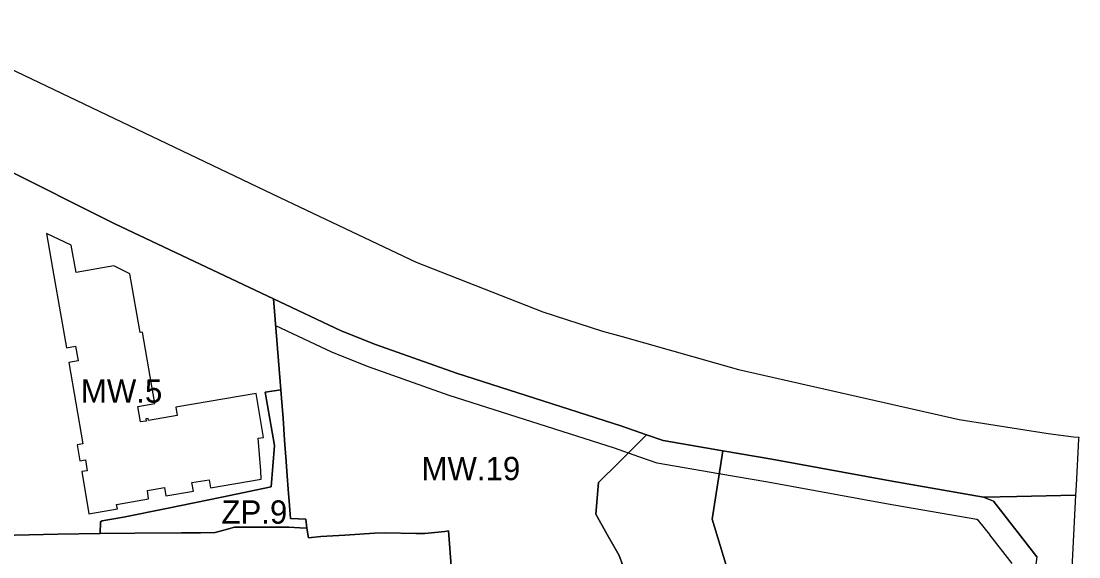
# Model space of a CAD drawing. Extents: x 7429178 to 7430831, y 5550228 to 5551611.
# Drawn here: x 7430227.9 to 7430454.6, y 5551215.2 to 5551330.1 of the extents above; entities that cross this region are included whole.
import ezdxf

# ---------------------------------------------------------------- set-up
doc = ezdxf.new("R2010")
doc.units = 0
for name, color, linetype in [('linie rozgraniczające', 7, 'Continuous'), ('nieprzekraczalne linie zabudowy', 7, 'Continuous'), ('obowiazujace linie zabudowy', 7, 'Continuous'), ('przeznaczenia terenów', 7, 'Continuous')]:
    doc.layers.add(name, color=color, linetype=linetype)

msp = doc.modelspace()

# ---------------------------------------------------------------- linework, layer by layer
at = {"layer": 'linie rozgraniczające'}
for points in [[(7430204.21, 5551330.07), (7430283.32, 5551292.27), (7430287.53, 5551290.26), (7430312.6, 5551278.38), (7430339.69, 5551267.71), (7430352.52, 5551263.63), (7430356.74, 5551262.44), (7430381.68, 5551255.38), (7430428.93, 5551244.66), (7430448.02, 5551241.65), (7430453.5, 5551240.96), (7430454.62, 5551240.86), (7430454.55, 5551240.42), (7430454.03, 5551230.54), (7430453.92, 5551228.43), (7430441.32, 5551228.16), (7430434.2, 5551228.01), (7430414.19, 5551231.47), (7430388.84, 5551236.12), (7430378.33, 5551237.93), (7430365.52, 5551240.14), (7430361.96, 5551241.38), (7430356.69, 5551243.22), (7430321.24, 5551254.57), (7430303.88, 5551260.71), (7430296.47, 5551263.67), (7430281.98, 5551270.52), (7430247.95, 5551286.58), (7430223.25, 5551298.98)], [(7430223.25, 5551298.98), (7430247.95, 5551286.58), (7430281.98, 5551270.52), (7430283.58, 5551251.03), (7430280.24, 5551250.54), (7430282.2, 5551239.08), (7430281.46, 5551230.21), (7430270.9, 5551228.02), (7430259.03, 5551225.56), (7430249.81, 5551223.69), (7430245.26, 5551222.91), (7430244.89, 5551222.69), (7430244.86, 5551220.19), (7430235.76, 5551220.1), (7430223.44, 5551219.78)], [(7430320.11, 5551212.36), (7430319.52, 5551220.76), (7430318.71, 5551220.67), (7430314.4, 5551220.21), (7430312.53, 5551220.18), (7430306.02, 5551220.33), (7430303.62, 5551220.29), (7430297.25, 5551219.84), (7430292.15, 5551219.54), (7430289.51, 5551219.29), (7430289.12, 5551221.34), (7430288.9, 5551223.27), (7430285.62, 5551223.41), (7430285.42, 5551226.18), (7430285.16, 5551229.69), (7430284.94, 5551232.6), (7430284.72, 5551235.62), (7430284.38, 5551240.23), (7430284.03, 5551244.91), (7430283.78, 5551248.27), (7430283.58, 5551251.03), (7430281.98, 5551270.52), (7430296.47, 5551263.67), (7430303.88, 5551260.71), (7430321.24, 5551254.57), (7430356.69, 5551243.22), (7430361.96, 5551241.38), (7430360.49, 5551239.92), (7430356.05, 5551235.5), (7430351.65, 5551231.12), (7430351.05, 5551224.34), (7430353.53, 5551219.97), (7430356.08, 5551215.49), (7430357.63, 5551211.22)], [(7430357.63, 5551211.22), (7430356.08, 5551215.49), (7430353.53, 5551219.97), (7430351.05, 5551224.34), (7430351.65, 5551231.12), (7430356.05, 5551235.5), (7430360.49, 5551239.92), (7430361.96, 5551241.38), (7430365.52, 5551240.14), (7430378.33, 5551237.93), (7430376.02, 5551223.29), (7430380.2, 5551209.64)], [(7430445.59, 5551215.17), (7430436.29, 5551227.12), (7430434.2, 5551228.01), (7430441.32, 5551228.16), (7430453.92, 5551228.43), (7430452.8, 5551207.06)], [(7430223.44, 5551219.78), (7430235.76, 5551220.1), (7430244.86, 5551220.19), (7430252.3, 5551220.28), (7430262.29, 5551220.38), (7430266.36, 5551220.38), (7430269.5, 5551220.41), (7430271.38, 5551220.94), (7430273.62, 5551221.58), (7430279.07, 5551221.57), (7430283.09, 5551221.56), (7430285.27, 5551221.54), (7430287.65, 5551221.42), (7430289.12, 5551221.34), (7430289.51, 5551219.29), (7430292.15, 5551219.54), (7430297.25, 5551219.84), (7430303.62, 5551220.29), (7430306.02, 5551220.33), (7430312.53, 5551220.18), (7430314.4, 5551220.21), (7430318.71, 5551220.67), (7430319.52, 5551220.76), (7430320.11, 5551212.36)]]:
    msp.add_lwpolyline(points, dxfattribs=at)
for points in [[(7430244.86, 5551220.19), (7430244.89, 5551222.69), (7430245.26, 5551222.91), (7430249.81, 5551223.69), (7430259.03, 5551225.56), (7430270.9, 5551228.02), (7430281.46, 5551230.21), (7430282.2, 5551239.08), (7430280.24, 5551250.54), (7430283.58, 5551251.03), (7430283.78, 5551248.27), (7430284.03, 5551244.91), (7430284.38, 5551240.23), (7430284.72, 5551235.62), (7430284.94, 5551232.6), (7430285.16, 5551229.69), (7430285.42, 5551226.18), (7430285.62, 5551223.41), (7430288.9, 5551223.27), (7430289.12, 5551221.34), (7430287.65, 5551221.42), (7430285.27, 5551221.54), (7430283.09, 5551221.56), (7430279.07, 5551221.57), (7430273.62, 5551221.58), (7430271.38, 5551220.94), (7430269.5, 5551220.41), (7430266.36, 5551220.38), (7430262.29, 5551220.38), (7430252.3, 5551220.28)], [(7430411.61, 5551158.64), (7430406.82, 5551154.03), (7430401.87, 5551161.62), (7430397.6, 5551168.16), (7430392.26, 5551176.35), (7430388.73, 5551181.76), (7430384.53, 5551195.49), (7430380.2, 5551209.64), (7430376.02, 5551223.29), (7430378.33, 5551237.93), (7430388.84, 5551236.12), (7430414.19, 5551231.47), (7430434.2, 5551228.01), (7430436.29, 5551227.12), (7430445.59, 5551215.17), (7430444.52, 5551207.22), (7430442.56, 5551198.65), (7430441.54, 5551194.19), (7430438.73, 5551188.59), (7430435.8, 5551182.74), (7430432.52, 5551178.26), (7430430.09, 5551175.69), (7430422.42, 5551168.61)]]:
    msp.add_lwpolyline(points, close=True, dxfattribs=at)
at = {"layer": 'nieprzekraczalne linie zabudowy'}
msp.add_lwpolyline([(7430440.35, 5551213.76), (7430435.54, 5551219.95), (7430435.53, 5551219.96), (7430433.14, 5551223.02), (7430432.78, 5551223.18), (7430413.32, 5551226.54), (7430387.97, 5551231.19), (7430377.48, 5551233), (7430364.26, 5551235.28), (7430360.31, 5551236.66), (7430355.1, 5551238.48), (7430319.64, 5551249.83), (7430302.12, 5551256.03), (7430294.47, 5551259.09), (7430282.46, 5551264.76)], dxfattribs=at)
at = {"layer": 'obowiazujace linie zabudowy'}
msp.add_lwpolyline([(7430237.59, 5551260), (7430239.57, 5551260.36), (7430240.13, 5551257.2), (7430238.13, 5551256.86), (7430241.14, 5551239.41), (7430239.89, 5551239.19), (7430240.49, 5551235.79), (7430241.66, 5551235.99), (7430242.06, 5551233.68), (7430240.88, 5551233.47), (7430242.43, 5551224.46), (7430248.53, 5551225.5), (7430248.37, 5551226.46), (7430255.23, 5551227.66), (7430254.95, 5551229.43), (7430258.63, 5551230.07), (7430258.94, 5551228.29), (7430264.82, 5551229.32), (7430264.5, 5551231.11), (7430268.21, 5551231.75), (7430268.52, 5551229.97), (7430279.33, 5551231.87), (7430279.24, 5551233.65), (7430278.67, 5551240.63), (7430279.88, 5551240.79), (7430278.26, 5551250.25), (7430261.04, 5551247.31), (7430261.37, 5551245.5), (7430255.17, 5551244.41), (7430255.09, 5551244.85), (7430254.64, 5551244.77), (7430254.72, 5551244.33), (7430253.5, 5551244.13), (7430252.92, 5551247.42), (7430256.55, 5551248.07), (7430253.9, 5551263.41), (7430253.41, 5551263.34), (7430251.23, 5551275.92), (7430247.75, 5551277.59), (7430239.66, 5551276.19), (7430238.65, 5551282.01), (7430233.35, 5551284.54), (7430234.92, 5551275.46), (7430237.59, 5551260)], dxfattribs=at)

# ---------------------------------------------------------------- texts
at = {"layer": 'przeznaczenia terenów'}
for s, p in [('MW.5', (7430240.7, 5551248.27)), ('MW.19', (7430313.71, 5551231.64)), ('ZP.9', (7430270.83, 5551222.31))]:
    msp.add_text(s, height=5, dxfattribs=at).set_placement(p)

doc.saveas('drawing.dxf')
